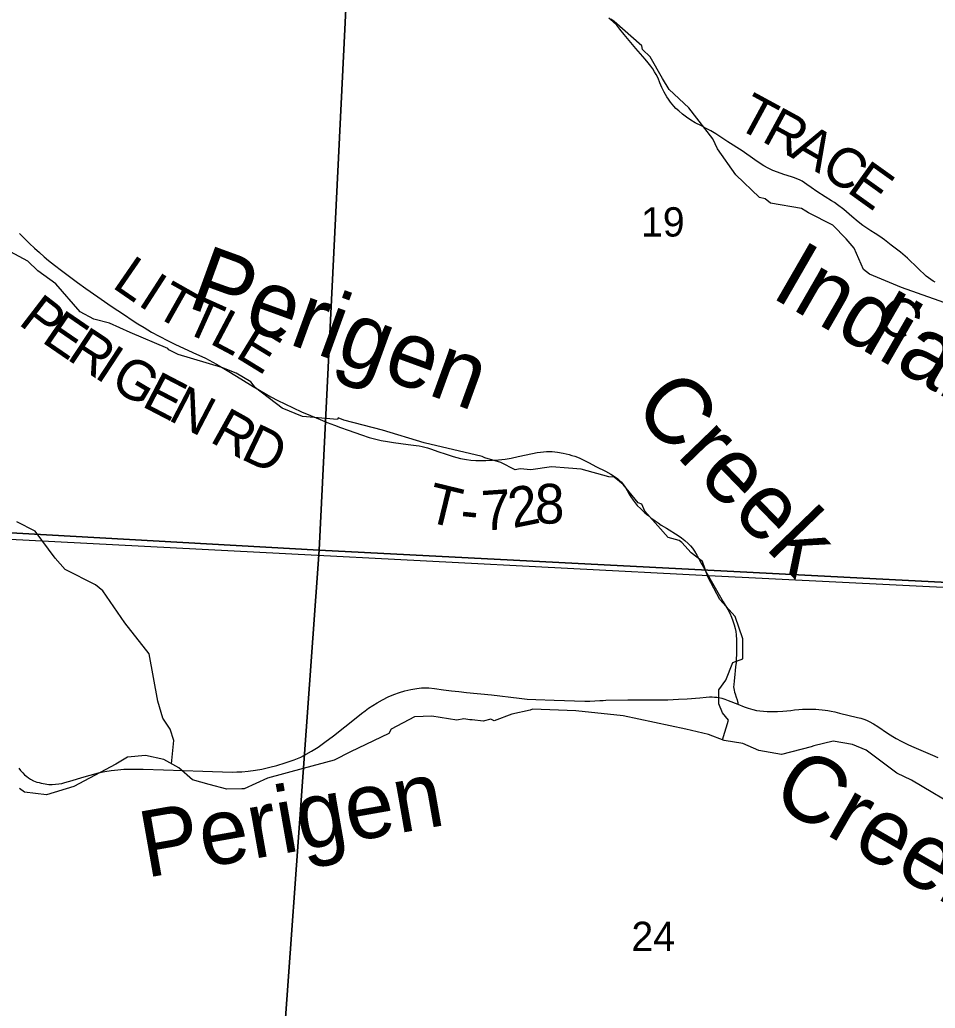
# Model space of a CAD drawing. Extents: x 396.2 to 468.4, y 232.6 to 279.1.
# Drawn here: x 416.888 to 418.195, y 269.775 to 271.187 of the extents above; entities that cross this region are included whole.
import ezdxf

# ---------------------------------------------------------------- set-up
doc = ezdxf.new("R2010")
doc.units = 0
for name, color, linetype in [('Default', 7, 'Continuous'), ('GM_X_County_Road', 7, 'Continuous'), ('GM_X_County_Road_Text', 7, 'Continuous'), ('GM_X_Minor_River', 7, 'Continuous'), ('GM_X_Minor_River_Text', 7, 'Continuous'), ('GM_X_Section', 7, 'Continuous'), ('GM_X_Section_Text', 7, 'Continuous'), ('GM_X_State_Route', 7, 'Continuous'), ('GM_X_Township', 7, 'Continuous'), ('GM_X_Township_Road', 7, 'Continuous'), ('GM_X_Township_Road_Text', 7, 'Continuous')]:
    doc.layers.add(name, color=color, linetype=linetype)

msp = doc.modelspace()

# ---------------------------------------------------------------- linework, layer by layer
at = {"layer": 'Default'}
msp.add_lwpolyline([(420.4241, 270.2645), (419.658, 270.3039), (418.8718, 270.3435), (418.5989, 270.3564), (417.8712, 270.3927), (416.2596, 270.4764), (415.4605, 270.5176), (415.2459, 270.5284), (415.1765, 269.4523), (415.0934, 268.0402), (415.0582, 267.4588), (415.0293, 266.9964)], dxfattribs=at)
at = {"layer": 'GM_X_County_Road'}
msp.add_lwpolyline([(418.1953, 270.8121), (418.1922, 270.8138), (418.1889, 270.8159), (418.1858, 270.8181), (418.1825, 270.8206), (418.1703, 270.8321), (418.1555, 270.8464), (418.1456, 270.8549), (418.1325, 270.8652), (418.1228, 270.8726), (418.1163, 270.8773), (418.1095, 270.8817), (418.1033, 270.8856), (418.0975, 270.8894), (418.0918, 270.8933), (418.0852, 270.8985), (418.0762, 270.9059), (418.0645, 270.9159), (418.0558, 270.9228), (418.0513, 270.9258), (418.0473, 270.9284), (418.0379, 270.9342), (418.0259, 270.9418), (418.0181, 270.9472), (418.012, 270.9516), (418.005, 270.9563), (418.0013, 270.9582), (417.9977, 270.9599), (417.994, 270.9612), (417.9899, 270.9625), (417.9792, 270.9659), (417.9697, 270.9691), (417.9633, 270.9717), (417.9565, 270.9749), (417.9505, 270.9782), (417.9437, 270.9826), (417.9376, 270.9868), (417.9193, 270.9996), (417.8991, 271.0128), (417.8819, 271.0238), (417.8745, 271.0282), (417.8681, 271.0317), (417.8614, 271.0352), (417.8525, 271.0398), (417.846, 271.0436), (417.8398, 271.0478), (417.8343, 271.0521), (417.8288, 271.0567), (417.8249, 271.0603), (417.8217, 271.0637), (417.8172, 271.0692), (417.814, 271.0737), (417.8118, 271.0768), (417.808, 271.0833), (417.8048, 271.0901), (417.8019, 271.097), (417.7993, 271.1033), (417.7966, 271.1089), (417.7944, 271.1127), (417.7919, 271.1166), (417.7892, 271.1204), (417.7853, 271.1253), (417.7809, 271.1305), (417.7677, 271.1459), (417.7509, 271.1659), (417.7449, 271.1734), (417.7403, 271.179), (417.7349, 271.1843), (417.7291, 271.1894)], dxfattribs=at)
at = {"layer": 'GM_X_Minor_River'}
for points in [[(418.2237, 270.7776), (418.1469, 270.8044), (418.1015, 270.8237), (418.0928, 270.8302), (418.0796, 270.8605), (418.0682, 270.8742), (418.0489, 270.8935), (418.0141, 270.9113), (418.0103, 270.9136), (418.0043, 270.9174), (417.9597, 270.9252), (417.9521, 270.9313), (417.9442, 270.9332), (417.9105, 270.9654), (417.8844, 271.0026), (417.8775, 271.017), (417.8431, 271.0611), (417.8151, 271.0872), (417.8056, 271.1028), (417.7882, 271.1339), (417.7772, 271.1445), (417.7761, 271.1495), (417.7364, 271.1843), (417.7318, 271.1877)], [(417.8913, 270.1587), (417.8999, 270.1866), (417.8912, 270.1968), (417.8859, 270.2097), (417.8863, 270.2299), (417.8961, 270.2439), (417.9063, 270.2691), (417.9203, 270.274), (417.9206, 270.2805), (417.9202, 270.3025), (417.9096, 270.3344), (417.8877, 270.3591), (417.8702, 270.3914), (417.863, 270.4134), (417.8468, 270.4255), (417.8335, 270.4403), (417.8297, 270.4433), (417.8139, 270.4475), (417.7802, 270.485), (417.776, 270.4949), (417.7707, 270.4968), (417.7495, 270.5233), (417.7367, 270.5336), (417.7291, 270.5339), (417.6894, 270.5452), (417.6716, 270.5463), (417.6471, 270.5485), (417.6176, 270.5443), (417.6021, 270.5454), (417.5953, 270.5439), (417.5748, 270.5548), (417.5518, 270.5612), (417.548, 270.5631), (417.4652, 270.5827), (417.4058, 270.6008), (417.3506, 270.6151), (417.3423, 270.6185), (417.3415, 270.6162), (417.2913, 270.6203), (417.2625, 270.6324), (417.2243, 270.6612), (417.2175, 270.6699), (417.1967, 270.6824), (417.1763, 270.6903), (417.1139, 270.7088), (417.1003, 270.7156), (417.0988, 270.7175), (417.0451, 270.7402), (417.0159, 270.7534), (416.9933, 270.7594), (416.974, 270.77), (416.9388, 270.8098), (416.9134, 270.8284), (416.899, 270.8421), (416.8499, 270.8682)], [(417.1043, 270.1243), (417.1078, 270.1575), (417.1022, 270.1736), (417.0917, 270.1892), (417.0849, 270.2137), (417.0726, 270.2813), (417.0376, 270.3257), (417.0061, 270.3715), (416.9958, 270.3798), (416.9526, 270.4017), (416.938, 270.4177), (416.9093, 270.4566), (416.8832, 270.47)], [(417.6199, 270.2022), (417.6164, 270.2007), (417.5903, 270.1953), (417.5654, 270.1857), (417.5605, 270.188), (417.5495, 270.1853), (417.534, 270.1868), (417.5302, 270.1868), (417.5219, 270.1887), (417.5121, 270.1867), (417.4762, 270.1923), (417.4512, 270.1911), (417.418, 270.1736), (417.4146, 270.1675), (417.3598, 270.1415), (417.3364, 270.1293), (417.2925, 270.1174), (417.2415, 270.1036), (417.2079, 270.0883), (417.2045, 270.0883), (417.1833, 270.0882), (417.1583, 270.0946), (417.1341, 270.1014), (417.1149, 270.1185), (417.0933, 270.1302), (417.0672, 270.1362), (417.0415, 270.1335), (417.0249, 270.1239), (416.9648, 270.0919), (416.9255, 270.08), (416.8945, 270.0837), (416.8869, 270.089)], [(418.235, 270.057), (418.1612, 270.1009), (418.1404, 270.1111), (418.0965, 270.1437), (418.0772, 270.152), (418.0493, 270.1565), (418.0217, 270.15), (418.0179, 270.1485), (417.9756, 270.1377), (417.9434, 270.143), (417.9204, 270.1532), (417.8939, 270.1577), (417.8716, 270.1663), (417.8391, 270.1735), (417.7495, 270.1926), (417.6818, 270.1997), (417.6199, 270.2022)]]:
    msp.add_lwpolyline(points, dxfattribs=at)
at = {"layer": 'GM_X_Section'}
for points in [[(416.3419, 271.497), (417.365, 271.4443), (417.3152, 270.4295), (416.2648, 270.4883)], [(417.365, 271.4443), (418.4006, 271.3893), (418.3421, 270.3767), (417.3152, 270.4295)], [(416.2648, 270.4883), (417.3152, 270.4295), (417.2412, 269.4041), (416.2139, 269.4538)], [(417.3152, 270.4295), (418.3421, 270.3767), (418.2741, 269.3589), (417.2412, 269.4041)]]:
    msp.add_lwpolyline(points, close=True, dxfattribs=at)
at = {"layer": 'GM_X_State_Route'}
msp.add_lwpolyline([(416.8862, 270.1181), (416.8888, 270.1148), (416.8918, 270.1113), (416.8945, 270.1086), (416.8974, 270.1059), (416.9, 270.104), (416.9027, 270.1023), (416.907, 270.1001), (416.9096, 270.0991), (416.9121, 270.0982), (416.915, 270.0973), (416.918, 270.0965), (416.9208, 270.0959), (416.9237, 270.0955), (416.9263, 270.0951), (416.9289, 270.0949), (416.9314, 270.0948), (416.9339, 270.0948), (416.9384, 270.0951), (416.9431, 270.0955), (416.9474, 270.0963), (416.952, 270.0973), (416.9626, 270.1003), (416.9761, 270.1047), (416.9879, 270.1082), (417.0001, 270.1112), (417.0091, 270.1132), (417.0182, 270.1147), (417.0275, 270.1158), (417.0363, 270.1164), (417.0446, 270.1167), (417.0537, 270.1167), (417.0636, 270.1164), (417.0928, 270.1155), (417.1489, 270.1135), (417.1907, 270.1125), (417.1978, 270.1126), (417.2046, 270.1129), (417.2138, 270.1137), (417.2243, 270.1151), (417.2335, 270.1168), (417.2445, 270.1193), (417.2547, 270.122), (417.2666, 270.1256), (417.2796, 270.13), (417.2888, 270.1339), (417.2967, 270.1378), (417.3043, 270.1421), (417.3137, 270.1482), (417.3234, 270.155), (417.3359, 270.1643), (417.3682, 270.19), (417.3758, 270.1961), (417.3808, 270.2), (417.3858, 270.2037), (417.3917, 270.2077), (417.3981, 270.2115), (417.4057, 270.2156), (417.414, 270.2197), (417.422, 270.223), (417.4301, 270.226), (417.4378, 270.2284), (417.4462, 270.2304), (417.4547, 270.232), (417.4614, 270.2326), (417.4657, 270.2328), (417.4718, 270.2327), (417.4798, 270.2319), (417.4927, 270.2301), (417.5044, 270.2285), (417.5145, 270.2273), (417.5257, 270.2261), (417.5614, 270.2229), (417.6007, 270.2178), (417.6124, 270.2167), (417.6246, 270.2161), (417.651, 270.2151), (417.6947, 270.2138), (417.7019, 270.2137), (417.7163, 270.2145), (417.7208, 270.2148), (417.7248, 270.2149), (417.7562, 270.2155), (417.7921, 270.2156), (417.8133, 270.2158), (417.8284, 270.2164), (417.8409, 270.217), (417.8591, 270.2186), (417.8681, 270.2195), (417.873, 270.2198), (417.8767, 270.2198), (417.88, 270.2196), (417.8833, 270.2193), (417.8862, 270.2189), (417.8902, 270.2178), (417.8945, 270.2165), (417.8995, 270.2148), (417.9135, 270.2092), (417.9223, 270.2057), (417.9279, 270.2037), (417.9345, 270.2019), (417.9398, 270.2005), (417.9445, 270.1997), (417.9497, 270.1992), (417.9553, 270.1989), (417.9701, 270.1989), (417.9775, 270.1992), (417.9835, 270.1997), (417.9888, 270.2004), (417.9944, 270.2011), (418.0003, 270.2018), (418.0056, 270.2022), (418.0114, 270.2024), (418.0159, 270.2024), (418.0206, 270.2024), (418.0248, 270.2022), (418.0292, 270.2019), (418.0339, 270.2015), (418.0379, 270.201), (418.0419, 270.2004), (418.0468, 270.1994), (418.0519, 270.1983), (418.0586, 270.1967), (418.0844, 270.1906), (418.0888, 270.1894), (418.0934, 270.188), (418.0972, 270.1865), (418.1008, 270.1848), (418.1071, 270.1813), (418.1134, 270.1774), (418.1271, 270.1679), (418.1345, 270.1631), (418.1393, 270.1603), (418.1465, 270.1564), (418.1572, 270.1513), (418.1646, 270.1481), (418.1845, 270.1394), (418.1913, 270.1364), (418.1988, 270.1333)], dxfattribs=at)
at = {"layer": 'GM_X_Township'}
msp.add_lwpolyline([(418.5989, 270.3564), (417.8712, 270.3927), (416.2596, 270.4764), (415.4605, 270.5176)], dxfattribs=at)
at = {"layer": 'GM_X_Township_Road'}
for points in [[(416.8871, 270.8818), (416.9016, 270.8675), (416.9086, 270.8607), (416.9157, 270.8543), (416.9222, 270.8484), (416.9284, 270.8433), (416.937, 270.8364), (416.9473, 270.8287), (416.9584, 270.8204), (416.9701, 270.8117), (416.9819, 270.8029), (416.999, 270.7912), (417.0182, 270.778), (417.0371, 270.7653), (417.048, 270.758), (417.0562, 270.7526), (417.065, 270.7472), (417.0759, 270.7408), (417.0868, 270.7348), (417.0995, 270.7283), (417.109, 270.7237), (417.1348, 270.7119), (417.1528, 270.7034), (417.1687, 270.6948), (417.1861, 270.6847), (417.2034, 270.6742), (417.2208, 270.6631), (417.23, 270.6578), (417.2379, 270.6532), (417.2461, 270.6486), (417.2563, 270.6433), (417.2664, 270.6382), (417.278, 270.6326), (417.2902, 270.6271), (417.3029, 270.6217), (417.3165, 270.616), (417.3268, 270.6117), (417.3371, 270.6077), (417.3459, 270.6044), (417.3565, 270.6008), (417.366, 270.5974), (417.3758, 270.594), (417.3864, 270.5905), (417.3942, 270.5884), (417.4039, 270.5861), (417.413, 270.5845), (417.4216, 270.5832), (417.432, 270.5819), (417.4424, 270.5805), (417.4539, 270.5789), (417.4581, 270.5782), (417.4622, 270.5773), (417.4662, 270.5763), (417.4701, 270.5753), (417.4759, 270.5735), (417.4847, 270.5705), (417.4964, 270.5664), (417.5065, 270.5632), (417.5121, 270.5618), (417.5173, 270.5604), (417.5258, 270.5587), (417.532, 270.5578), (417.5389, 270.5573), (417.5455, 270.5572), (417.5534, 270.5573), (417.5629, 270.5578), (417.5714, 270.5584), (417.5807, 270.5593), (417.5893, 270.5607), (417.5997, 270.563), (417.6108, 270.5655), (417.6267, 270.5688), (417.6316, 270.5695), (417.6355, 270.57), (417.64, 270.5703), (417.6438, 270.5703), (417.6479, 270.5702), (417.6519, 270.5697), (417.6558, 270.5692), (417.6639, 270.5678), (417.6682, 270.5669), (417.6725, 270.5659), (417.6762, 270.5648), (417.6802, 270.5636), (417.684, 270.5622), (417.6877, 270.5606), (417.6999, 270.5545), (417.7114, 270.5484), (417.7241, 270.542), (417.7317, 270.5378), (417.7371, 270.5344), (417.7412, 270.5315), (417.7441, 270.529), (417.7471, 270.5263), (417.7498, 270.5229), (417.7527, 270.5189), (417.7552, 270.5146), (417.7573, 270.5108), (417.7605, 270.5054), (417.7636, 270.5008), (417.7665, 270.4968), (417.7697, 270.4931), (417.7746, 270.4882), (417.7806, 270.4828), (417.7849, 270.4792), (417.7892, 270.4757), (417.7952, 270.4712), (417.7994, 270.4682), (417.8039, 270.4652), (417.8112, 270.4606), (417.8281, 270.4501), (417.8327, 270.447), (417.8376, 270.4433), (417.8423, 270.4391), (417.8457, 270.4356), (417.8485, 270.4322), (417.8513, 270.4281), (417.8548, 270.4222), (417.8611, 270.4108), (417.8644, 270.4049), (417.8676, 270.3989), (417.8714, 270.3922)], [(417.8714, 270.3922), (417.879, 270.3789), (417.8923, 270.3558), (417.8991, 270.3444), (417.9019, 270.3392), (417.9043, 270.3336), (417.9063, 270.3282), (417.908, 270.3229), (417.9094, 270.3175), (417.9103, 270.3131), (417.9108, 270.3083), (417.9112, 270.3013), (417.9114, 270.2936), (417.9115, 270.2898), (417.9115, 270.2853), (417.9113, 270.2801), (417.9111, 270.2746), (417.9107, 270.2687), (417.9101, 270.2629), (417.9095, 270.2573), (417.9089, 270.2518), (417.9079, 270.2427), (417.9074, 270.2369), (417.9073, 270.2344), (417.9075, 270.232), (417.9078, 270.2295), (417.9085, 270.2265), (417.9093, 270.2242), (417.911, 270.2196), (417.9123, 270.2155), (417.9129, 270.2133), (417.9131, 270.2119), (417.9135, 270.2092)]]:
    msp.add_lwpolyline(points, dxfattribs=at)

# ---------------------------------------------------------------- texts
at = {"layer": 'GM_X_County_Road_Text'}
for s, rotation, p in [('T', 331.5142, (417.9082, 271.0344)), ('R', 331.4553, (417.9455, 271.0142)), ('A', 329.9809, (417.9862, 270.992)), ('C', 326.58, (418.0287, 270.9675)), ('E', 324.4262, (418.0672, 270.9421)), ('C', 321.4094, (418.1051, 270.7572)), ('-', 348.5859, (418.168, 270.7158))]:
    msp.add_text(s, height=0.0568, rotation=rotation, dxfattribs=at).set_placement(p)
at = {"layer": 'GM_X_Minor_River_Text'}
for s, height, rotation, p in [('Perigen', 0.09469, 340.0029, (417.1245, 270.7773)), ('Indian', 0.0947, 330.0018, (417.9584, 270.7919)), ('Creek', 0.0947, 314.0019, (417.7609, 270.6295)), ('Creek', 0.09469, 330.0049, (417.9577, 270.0702)), ('Perigen', 0.0947, 10.0083, (417.068, 269.9613))]:
    msp.add_text(s, height=height, rotation=rotation, dxfattribs=at).set_placement(p)
at = {"layer": 'GM_X_Section_Text'}
for s, p in [('19', (417.775, 270.8773)), ('24', (417.7613, 269.8568))]:
    msp.add_text(s, height=0.04186, rotation=0, dxfattribs=at).set_placement(p)
at = {"layer": 'GM_X_Township_Road_Text'}
for s, rotation, p in [('L', 325.4107, (417.0178, 270.8056)), ('I', 327.159, (417.0544, 270.7804)), ('T', 330.5158, (417.077, 270.7659)), ('P', 322.463, (416.884, 270.753)), ('T', 335.7988, (417.119, 270.7425)), ('E', 325.5485, (416.9171, 270.7277)), ('L', 332.1047, (417.1569, 270.7255)), ('E', 328.4839, (417.1937, 270.706)), ('R', 326.635, (416.9531, 270.703)), ('I', 326.7269, (416.9922, 270.6773)), ('G', 329.3578, (417.0141, 270.6629)), ('E', 332.4783, (417.0601, 270.6358)), ('N', 332.4428, (417.0978, 270.6162)), ('R', 330.8612, (417.1572, 270.5851)), ('D', 334.4086, (417.2014, 270.5606)), ('T', 346.3411, (417.4656, 270.4711)), ('8', 359.9349, (417.6233, 270.4673)), ('7', 3.9594, (417.549, 270.4571)), ('2', 11.512, (417.592, 270.4606)), ('-', 354.1829, (417.5152, 270.4596))]:
    msp.add_text(s, height=0.0568, rotation=rotation, dxfattribs=at).set_placement(p)

doc.saveas('drawing.dxf')
